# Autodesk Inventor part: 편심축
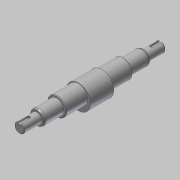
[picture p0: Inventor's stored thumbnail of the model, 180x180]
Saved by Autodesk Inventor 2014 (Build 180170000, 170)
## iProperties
Created: 2015-10
Part Number: 편심축
Document SubType Name: Modeling
Designer: mdu
Density: 1 g/cm^3
Material: 강철, 연강
Mass: 168.947 g
Surface Area: 248.524 cm^2
Volume: 168.947 cm^3
Appearance: 강철
Author: mdu
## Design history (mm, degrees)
sketch "스케치6"
  geometry: L1 (-121, 0)-(121, 0); L2 (-121, 0)-(-121, 8.5); L3 (-121, 8.5)-(-91, 8.5); L4 (-91, 8.5)-(-91, 12.5); L5 (-91, 12.5)-(-57, 12.5); L6 (-57, 12.5)-(-57, 16); L7 (-57, 16)-(57, 16); L8 (57, 16)-(57, 12.5); L9 (57, 12.5)-(91, 12.5); L10 (91, 12.5)-(91, 8.5); L11 (91, 8.5)-(121, 8.5); L12 (121, 8.5)-(121, 0); 2 further points
  constraints: 24 end point, 7 parallel, 5 collinear, 2 perpendicular, 1 coincident, 1 horizontal, 1 midpoint, 1 vertical
  dimensions: "d39" = 242 distance of L1.start L1.end; "d41" = 30 distance of L2.end L3.end; "d42" = 34 distance of L4.end L5.end; "d43" = 17 diameter of L3 L1; "d44" = 25 diameter of L5 L1; "d45" = 32 diameter of L7 L1; "d65" = 114 distance of L6.end L7.end (derived)
revolve "회전2" sketch "스케치6" stored, may be unused: angle "d46" = 90 deg
node "작업 평면4"
sketch "스케치7"
  geometry: C1 r 20.75 at (0, -4); 1 further point
  constraints: 1 centre point, 1 vertical alignment
  dimensions: "d47" = 41.5 diameter of C1; "d48" = 4 distance of C1.centre point (0, 0)
extrude "돌출4" join sketch "스케치7" stored distance "d49" = 40; taper "d50" = 0 deg
chamfer "모따기1" distance "d11" = 1; stored, may be unused: second distance "d12" = 2, angle "d13" = 45 deg
node "작업 평면5"
sketch "스케치8"
  geometry: L1 (15, 7.5)-(15, -7.5) reference; L2 (15, 2.5)-(-0.5, 2.5); L3 (-0.5, 2.5)-(-0.5, -2.5); L4 (-0.5, -2.5)-(15, -2.5); L5 (15, -2.5)-(15, 2.5); 2 further points
  constraints: 8 end point, 2 parallel, 1 horizontal, 1 horizontal alignment, 1 midpoint, 1 perpendicular, 1 point on line, 1 vertical alignment, 2 other
  dimensions: "d51" = 18 dimension on L1; "d52" = 5 distance between parallel lines of L2 L4
extrude "돌출5" cut sketch "스케치8" distance "d53" = 3; taper "d54" = 0 deg
sketch "스케치9"
  geometry: L1 (56, 16)-(57, 15) reference; L2 (57, 15)-(57, 12.5) reference; L3 (57, 12.5)-(91, 12.5) reference; L4 (91, 12.5)-(91, 8.5) reference; L5 (91, 8.5)-(103, 8.5) reference; L6 (103, 8.5)-(103, 5.5) reference; L7 (103, 5.5)-(121, 5.5) reference; L8 (121, 5.5)-(121, -7.5) reference; L9 (121, -7.5)-(120, -8.5) reference; L10 (120, -8.5)-(91, -8.5) reference; L11 (91, -8.5)-(91, -12.5) reference; L12 (91, -12.5)-(57, -12.5) reference; L13 (57, -12.5)-(57, -15) reference; L14 (57, -15)-(56, -16) reference; L15 (56, -16)-(20, -16) reference; L16 (20, -16)-(20, -24.75) reference; L17 (20, -24.75)-(-20, -24.75) reference; L18 (-20, -24.75)-(-20, -16) reference; L19 (-20, -16)-(-56, -16) reference; L20 (-56, -16)-(-57, -15) reference; L21 (-57, -15)-(-57, -12.5) reference; L22 (-57, -12.5)-(-91, -12.5) reference; L23 (-91, -12.5)-(-91, -8.5) reference; L24 (-91, -8.5)-(-120, -8.5) reference; L25 (-120, -8.5)-(-121, -7.5) reference; L26 (-121, -7.5)-(-121, 5.5) reference; L27 (-121, 5.5)-(-103, 5.5) reference; L28 (-103, 5.5)-(-103, 8.5) reference; L29 (-103, 8.5)-(-91, 8.5) reference; L30 (-91, 8.5)-(-91, 12.5) reference; L31 (-91, 12.5)-(-57, 12.5) reference; L32 (-57, 12.5)-(-57, 15) reference; L33 (-57, 15)-(-56, 16) reference; L34 (-56, 16)-(-20, 16) reference; L35 (-20, 16)-(-20, 16.75) reference; L36 (-20, 16.75)-(20, 16.75) reference; L37 (20, 16.75)-(20, 16) reference; L38 (20, 16)-(56, 16) reference; L39 (0, 0)-(-121, 0); L40 (-91, 11.25)-(-88.835, 12.5); L41 (-88.835, 12.5)-(-91, 12.5); L42 (-91, 12.5)-(-91, 11.25)
  constraints: 8 end point, 3 point on line, 1 collinear, 1 parallel, 1 perpendicular
  dimensions: "d55" = 22.5 diameter of L40.start L39; "d56" = 30 deg angle of L40 L31
revolve "회전3" sketch "스케치9" stored, may be unused: angle "d57" = 90 deg
sketch "스케치10"
  geometry: L1 (56, 16)-(57, 15) reference; L2 (57, 15)-(57, 12.5) reference; L3 (57, 12.5)-(91, 12.5) reference; L4 (91, 12.5)-(91, 8.5) reference; L5 (91, 8.5)-(103, 8.5) reference; L6 (103, 8.5)-(103, 5.5) reference; L7 (103, 5.5)-(121, 5.5) reference; L8 (121, 5.5)-(121, -7.5) reference; L9 (121, -7.5)-(120, -8.5) reference; L10 (120, -8.5)-(91, -8.5) reference; L11 (91, -8.5)-(91, -12.5) reference; L12 (91, -12.5)-(57, -12.5) reference; L13 (57, -12.5)-(57, -15) reference; L14 (57, -15)-(56, -16) reference; L15 (56, -16)-(20, -16) reference; L16 (20, -16)-(20, -24.75) reference; L17 (20, -24.75)-(-20, -24.75) reference; L18 (-20, -24.75)-(-20, -16) reference; L19 (-20, -16)-(-56, -16) reference; L20 (-56, -16)-(-57, -15) reference; L21 (-57, -15)-(-57, -12.5) reference; L22 (-57, -12.5)-(-88.835, -12.5) reference; L23 (-88.835, -12.5)-(-91, -11.25) reference; L24 (-91, -11.25)-(-91, -8.5) reference; L25 (-91, -8.5)-(-120, -8.5) reference; L26 (-120, -8.5)-(-121, -7.5) reference; L27 (-121, -7.5)-(-121, 5.5) reference; L28 (-121, 5.5)-(-103, 5.5) reference; L29 (-103, 5.5)-(-103, 8.5) reference; L30 (-103, 8.5)-(-91, 8.5) reference; L31 (-91, 8.5)-(-91, 11.25) reference; L32 (-91, 11.25)-(-88.835, 12.5) reference; L33 (-88.835, 12.5)-(-57, 12.5) reference; L34 (-57, 12.5)-(-57, 15) reference; L35 (-57, 15)-(-56, 16) reference; L36 (-56, 16)-(-20, 16) reference; L37 (-20, 16)-(-20, 16.75) reference; L38 (-20, 16.75)-(20, 16.75) reference; L39 (20, 16.75)-(20, 16) reference; L40 (20, 16)-(56, 16) reference; L41 (0, 0)-(121, 0); L42 (91, 11.25)-(88.835, 12.5); L43 (88.835, 12.5)-(91, 12.5); L44 (91, 12.5)-(91, 11.25)
  constraints: 8 end point, 3 point on line, 1 collinear, 1 parallel, 1 perpendicular
  dimensions: "d58" = 22.5 diameter of L42.start L41; "d59" = 30 deg angle of L42 L43
revolve "회전4" sketch "스케치10" stored, may be unused: angle "d60" = 90 deg
fillet "모깎기1" dims "d61" = 4, "d62" = 0.5
fillet "모깎기2" dims "d63" = 4, "d64" = 0.5
node "솔리드1"
mirror "대칭2"
node "절단 모서리 투영1"
node "절단 모서리 투영2"
other parameters: "d30" = 35
